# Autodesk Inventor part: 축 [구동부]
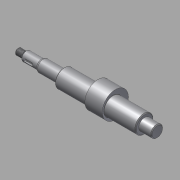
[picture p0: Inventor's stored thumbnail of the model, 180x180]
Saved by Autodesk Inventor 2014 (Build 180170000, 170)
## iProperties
Created: 2015-12
Part Number: 축 [구동부]
Document SubType Name: Modeling
Designer: mdu
Density: 7.86 g/cm^3
Material: 강철, 연강
Appearance: 강철
Mass: 489.709 g
Surface Area: 127.382 cm^2
Volume: 62.304 cm^3
Author: mdu
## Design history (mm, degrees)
sketch "스케치1"
  geometry: L1 (62, 100.9)-(62, 67.1) reference; L2 (51, 101.2)-(51, 84) reference; L3 (-51, 84)-(-51, 101.2) reference; L4 (-62, 67.1)-(-62, 100.9) reference; L5 (-51.6, 91.5)-(-61.4, 91.5) reference; L6 (51.6, 91.5)-(61.4, 91.5) reference; L7 (67, 84)-(-109, 84); L8 (-77, 64.201)-(-77, 103.799) reference; L9 (67, 84)-(67, 91.5); L10 (67, 91.5)-(51, 91.5); L11 (51, 91.5)-(51, 95.5); L12 (51, 95.5)-(-51, 95.5); L13 (-51, 95.5)-(-51, 91.5); L14 (-51, 91.5)-(-79, 91.5); L15 (-79, 91.5)-(-79, 90); L16 (-79, 90)-(-99, 90); L17 (-99, 90)-(-99, 87); L18 (-100.5, 88)-(-109, 88); L19 (-109, 88)-(-109, 84); L20 (-99, 87)-(-100.5, 87); L21 (-100.5, 87)-(-100.5, 88); 2 further points
  constraints: 32 end point, 7 parallel, 6 point on line, 5 perpendicular, 2 collinear, 2 horizontal, 1 midpoint, 4 other
  dimensions: "d0" = 5 distance from line of L7.start L1; "d2" = 2 distance between parallel lines of L15 L8; "d3" = 23 diameter of L12 L7; "d4" = 12 diameter of L16 L7; "d5" = 1.5 distance of L17.end L20.end; "d6" = 6 diameter of L20 L7; "d7" = 20 distance of L15.end L16.end; "d8" = 10 distance between parallel lines of L17 L19; "d9" = 8 diameter of L18 L7
revolve "회전1" sketch "스케치1" stored, may be unused: angle "d10" = 90 deg
sketch "스케치2"
  geometry: C1 r 11.5 at (84, 0) reference; C2 r 11.5 at (84, 0) reference; C3 r 16.5 at (87, 0); 1 further point
  constraints: 1 centre point, 1 horizontal alignment
  dimensions: "d11" = 33 diameter of C3; "d12" = 3 distance of C3.centre C1.centre
extrude "돌출1" join sketch "스케치2" stored distance "d13" = 22; taper "d14" = 0 deg
chamfer "모따기1" distance "d15" = 1; stored, may be unused: second distance "d16" = 2, angle "d17" = 45 deg
feature "스레드1" dims "d18" = 10, "d19" = 0
node "작업 평면1"
sketch "스케치3"
  geometry: L1 (-5, -2)-(3, -2); L2 (3, 2)-(-5, 2); L3 (-10, -5)-(-10, 5) reference; A1 r 2 centre (3, 0) between (3, -2) and (3, 2); A2 r 2 centre (-5, 0) between (-5, 2) and (-5, -2); 2 further points
  constraints: 4 end point, 4 point on circle, 4 tangent, 2 centre point, 1 horizontal, 1 horizontal alignment, 1 midpoint, 1 parallel
  dimensions: "d20" = 4 distance between parallel lines of L1 L2; "d21" = 12 dimension on A1 A2; "d22" = 3 distance edge to line of A2 L3
extrude "돌출2" cut sketch "스케치3" distance "d23" = 2.5; taper "d24" = 0 deg
fillet "모깎기1" dims "d25" = 0.3
fillet "모깎기2" dims "d26" = 3
node "솔리드1"
node "참조1"
node "참조2"
node "참조3"
node "참조4"
node "참조5"
node "투영된 루프1"
